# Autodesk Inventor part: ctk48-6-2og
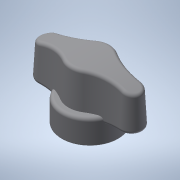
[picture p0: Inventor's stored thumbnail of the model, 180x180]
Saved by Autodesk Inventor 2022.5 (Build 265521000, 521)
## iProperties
Created: 2016-12
Part Number: ctk48-6-2og
Material: 一般
Document SubType Name: Modeling
Designer: imaocorp
Density: 1 g/cm^3
Appearance: 既定
Author: imaocorp
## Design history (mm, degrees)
node "ctk48-6-2og.x_t1"
node "ctk48-6-2og"
node "Base1"
